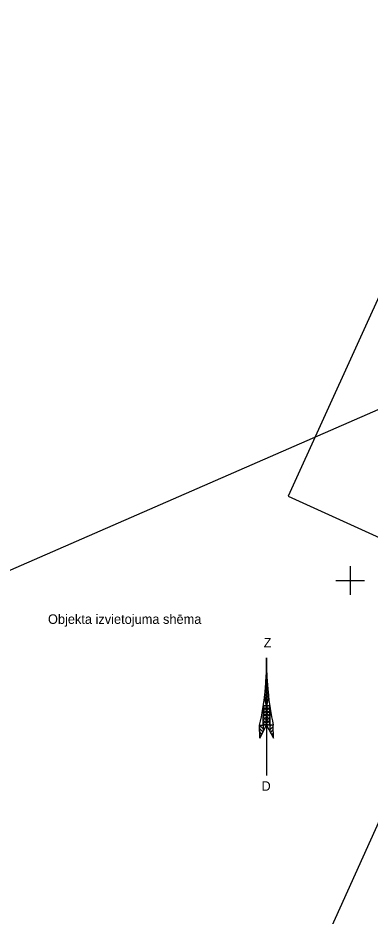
# Model space of a CAD drawing. Extents: x 616607 to 617499, y 408385 to 409695.
# Drawn here: x 616915.2 to 616952.1, y 408614.9 to 408708.9 of the extents above; entities that cross this region are included whole.
import ezdxf

# ---------------------------------------------------------------- set-up
doc = ezdxf.new("R2010")
doc.units = 0
for name, color, linetype in [('GEOD_ELEM_####_####_#', 7, 'Continuous'), ('RAMI_PLAN_####_TKST_#', 7, 'Continuous'), ('RAMI_UZMR_####_####_#', 7, 'Continuous')]:
    doc.layers.add(name, color=color, linetype=linetype)

# ---------------------------------------------------------------- blocks, each defined once
blk = doc.blocks.new('POINT_DISPLAY')
blk.add_line((0, 0), (0, 0))
blk = doc.blocks.new('KRUSTS')
at = {"layer": 'GEOD_ELEM_####_####_#'}
for p, q in [((0, 1.5), (0, 0)), ((-1.5, 0), (0, 0)), ((0, 0), (0, -1.5)), ((0, 0), (1.5, 0))]:
    blk.add_line(p, q, dxfattribs=at)

msp = doc.modelspace()

# ---------------------------------------------------------------- linework, layer by layer
at = {"layer": 'RAMI_PLAN_####_TKST_#'}
for p, q in [((617156.405, 409127.944), (616943.506, 408658.834)), ((616996.579, 408686.958), (616606.895, 408516.854)), ((616943.506, 408658.834), (617074.101, 408599.566)), ((616941.24, 408641.919), (616941.24, 408629.598)), ((616941.243, 408640.417), (616941.262, 408640.398)), ((616941.184, 408639.351), (616941.306, 408639.473)), ((616941.19, 408639.442), (616941.319, 408639.315)), ((616941.205, 408639.714), (616941.29, 408639.8)), ((616941.207, 408639.768), (616941.297, 408639.679)), ((616941.222, 408640.075), (616941.275, 408640.125)), ((616941.224, 408640.093), (616941.278, 408640.039)), ((616941.085, 408638.225), (616941.383, 408638.521)), ((616941.113, 408638.493), (616941.41, 408638.196)), ((616941.127, 408638.608), (616941.356, 408638.839)), ((616941.143, 408638.806), (616941.378, 408638.57)), ((616941.156, 408638.98), (616941.331, 408639.156)), ((616941.167, 408639.124), (616941.349, 408638.942)), ((616941.044, 408637.841), (616941.409, 408638.207)), ((616941.047, 408637.875), (616941.394, 408637.528)), ((616941.08, 408638.183), (616941.451, 408637.813)), ((616941.095, 408637.55), (616941.443, 408637.898)), ((616940.914, 408636.078), (616941.574, 408636.741)), ((616940.916, 408636.425), (616941.419, 408636.925)), ((616940.92, 408636.769), (616941.076, 408636.925)), ((616940.92, 408636.758), (616941.576, 408636.1)), ((616941.093, 408636.925), (616941.576, 408636.445)), ((616941.112, 408637.468), (616941.327, 408637.252)), ((616941.156, 408637.27), (616941.387, 408637.501)), ((616941.208, 408637.029), (616941.258, 408636.978)), ((616941.217, 408636.989), (616941.277, 408637.049)), ((616941.435, 408636.925), (616941.574, 408636.787)), ((616940.904, 408635.043), (616941.577, 408635.715)), ((616940.907, 408635.389), (616941.576, 408636.057)), ((616940.911, 408635.734), (616941.576, 408636.398)), ((616940.911, 408635.739), (616941.579, 408635.072)), ((616940.914, 408636.078), (616941.577, 408635.414)), ((616940.916, 408636.417), (616941.577, 408635.758)), ((616940.511, 408634.849), (616940.53, 408633.483)), ((616940.514, 408634.849), (616940.902, 408634.46)), ((616940.53, 408633.483), (616941.251, 408634.867)), ((616940.831, 408634.873), (616940.903, 408634.801)), ((616940.904, 408635.061), (616941.088, 408634.877)), ((616940.907, 408635.4), (616941.432, 408634.876)), ((616941.081, 408634.877), (616941.577, 408635.373)), ((616941.251, 408634.867), (616941.97, 408633.483)), ((616941.421, 408634.876), (616941.579, 408635.032)), ((616941.577, 408634.362), (616941.954, 408634.739)), ((616941.579, 408634.705), (616941.743, 408634.872)), ((616941.97, 408633.483), (616941.951, 408634.867)), ((616940.516, 408634.503), (616940.875, 408634.146)), ((616940.52, 408634.155), (616940.758, 408633.92)), ((616940.526, 408633.809), (616940.64, 408633.695)), ((616941.651, 408634.093), (616941.957, 408634.401)), ((616941.768, 408633.868), (616941.961, 408634.063)), ((616940.53, 408633.488), (616940.537, 408633.495)), ((616941.885, 408633.644), (616941.967, 408633.725))]:
    msp.add_line(p, q, dxfattribs=at)
for points in [[(616941.239, 408636.89), (616941.038, 408637.802), (616941.131, 408638.647), (616941.189, 408639.415), (616941.241, 408640.417), (616941.259, 408640.417), (616941.306, 408639.473), (616941.403, 408638.263), (616941.455, 408637.78)], [(616940.921, 408636.925), (616941.574, 408636.925), (616941.579, 408634.875), (616940.903, 408634.878)], [(616940.903, 408634.878), (616940.901, 408634.195), (616940.53, 408633.483), (616940.511, 408634.849)], [(616941.579, 408634.875), (616941.577, 408634.233), (616941.97, 408633.483), (616941.951, 408634.867)]]:
    msp.add_lwpolyline(points, close=True, dxfattribs=at)
for centre, radius, start, end in [((616914.142, 408641.141), 27.109, 346.57619, 1.64364), ((616973.372, 408641.597), 32.134, 179.42537, 192.08801)]:
    msp.add_arc(centre, radius, start, end, dxfattribs=at)
at = {"layer": 'RAMI_UZMR_####_####_#'}
msp.add_lwpolyline([(617191.828, 409115.62), (617145.545, 408952.8), (617072.809, 408766.141), (616965.332, 408652.076), (616939.432, 408594.661), (616924.839, 408592.467), (616706.433, 408526.081), (616666.426, 408467.691)], dxfattribs=at)

# ---------------------------------------------------------------- block references
at = {"layer": 'GEOD_ELEM_####_####_#'}
msp.add_blockref('KRUSTS', (616950, 408650), dxfattribs=at)
at = {"layer": 'RAMI_PLAN_####_TKST_#'}
msp.add_blockref('POINT_DISPLAY', (616941.97, 408633.485), dxfattribs=at)

# ---------------------------------------------------------------- texts
for s, p in [('Objekta izvietojuma shēma', (616918.371, 408645.467)), ('Z', (616940.949, 408643.002)), ('D', (616940.716, 408627.986))]:
    msp.add_text(s, height=1, dxfattribs=at).set_placement(p)

doc.saveas('drawing.dxf')
